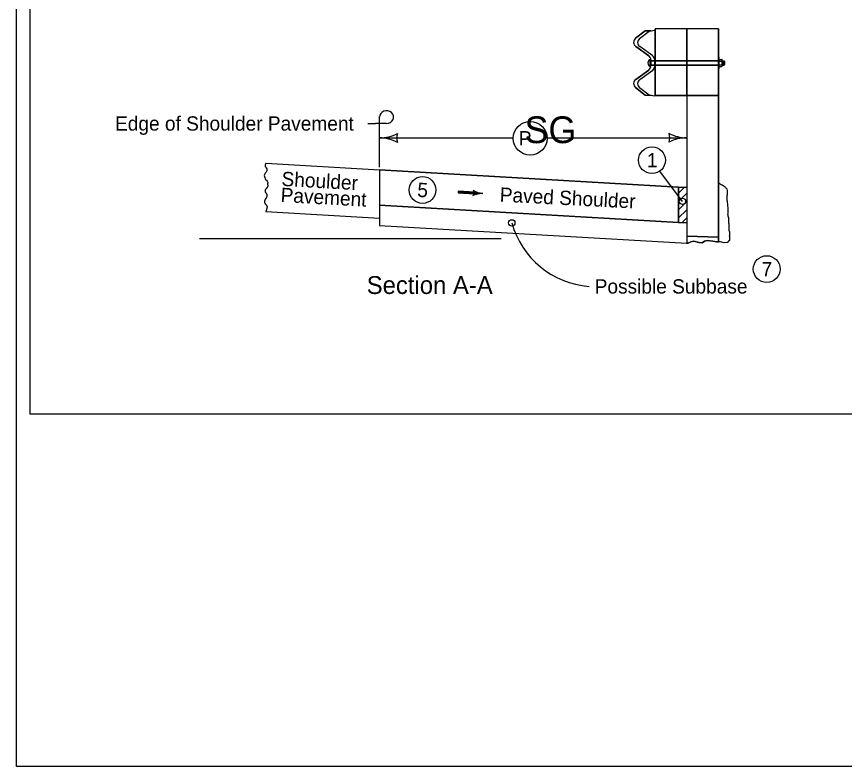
# Model space of a CAD drawing. Extents: x 9538 to 81668, y 7600 to 11751.
# Drawn here: x 24533 to 25461, y 7924 to 8764 of the extents above; entities that cross this region are included whole.
import ezdxf

# ---------------------------------------------------------------- set-up
doc = ezdxf.new("R2010")
doc.units = 0
for name, color, linetype in [('Default', 7, 'Continuous'), ('DsnShtMinorGrid13', 7, 'Continuous'), ('DsnShtMinorGrid14', 7, 'Continuous'), ('dsnStdCells', 7, 'Continuous'), ('dsnStdDimension', 7, 'Continuous'), ('dsnStdNameDate', 7, 'Continuous'), ('dsnStdNote', 7, 'Continuous'), ('dsnStdShading', 7, 'Continuous'), ('dsnStdTable', 7, 'Continuous')]:
    doc.layers.add(name, color=color, linetype=linetype)

msp = doc.modelspace()

# ---------------------------------------------------------------- linework, layer by layer
at = {"layer": 'Default'}
msp.add_lwpolyline([(24532.55, 9944.02), (27667.56, 9944.02), (27667.56, 7924.02), (24532.55, 7924.02)], close=True, dxfattribs=at)
at = {"layer": 'DsnShtMinorGrid13'}
for centre, radius in [((25244.81, 8603.28), 15), ((24987.61, 8569.91), 15), ((25278.94, 8557.17), 3.58), ((25373.4, 8481.26), 15)]:
    msp.add_circle(centre, radius, dxfattribs=at)
at = {"layer": 'DsnShtMinorGrid14'}
msp.add_circle((25087.64, 8533.07), 3.54, dxfattribs=at)
at = {"layer": 'dsnStdCells'}
for p, q in [((25226.58, 8730.73), (25241.09, 8720.31)), ((25241.09, 8704.24), (25226.58, 8693.82))]:
    msp.add_line(p, q, dxfattribs=at)
for points in [[(25230.83, 8739.63), (25230.82, 8739.62), (25241.6, 8748.02), (25243.48, 8748.36), (25237.15, 8748.24), (25226.39, 8739.85)], [(25283.87, 8714.93), (25283.87, 8750.61), (25248.33, 8750.61), (25248.33, 8714.93), (25248.33, 8714.93), (25283.87, 8714.93)], [(25319.42, 8714.93), (25319.42, 8718.93), (25319.42, 8750.61), (25283.87, 8750.61), (25283.87, 8714.93), (25319.42, 8714.93)], [(25245.54, 8720.09), (25245.57, 8720.07), (25231, 8730.53), (25231.03, 8730.51)], [(25243.49, 8715.68), (25243.49, 8714.6), (25247.93, 8714.6), (25247.93, 8715.46), (25247.93, 8715.46)], [(25248.33, 8714.6), (25248.33, 8709.93), (25248.33, 8709.93), (25283.87, 8709.93), (25283.87, 8714.6), (25248.33, 8714.6), (25248.33, 8714.6)], [(25319.42, 8709.93), (25319.42, 8714.6), (25283.87, 8714.6), (25283.87, 8709.93), (25319.42, 8709.93)], [(25247.93, 8708.65), (25247.93, 8708.65), (25247.93, 8709.93), (25243.49, 8709.93), (25243.49, 8708.87), (25243.49, 8709.93), (25243.49, 8709.93), (25243.49, 8708.87)], [(25248.33, 8709.6), (25248.33, 8675.96), (25283.87, 8675.96), (25283.87, 8709.6), (25248.33, 8709.6)], [(25319.42, 8675.96), (25319.42, 8705.6), (25319.42, 8709.6), (25283.87, 8709.6), (25283.87, 8675.96), (25319.42, 8675.96)], [(25231.03, 8693.6), (25231, 8693.58), (25245.57, 8704.04), (25245.54, 8704.02)], [(25226.39, 8684.7), (25237.15, 8676.31), (25244.26, 8675.62), (25241.6, 8676.09), (25230.82, 8684.5), (25230.83, 8684.48)], [(25319.42, 8517.01), (25319.42, 8675.96), (25283.87, 8675.96), (25283.87, 8572.99), (25283.87, 8566.3), (25283.87, 8566.3), (25283.87, 8566.3), (25283.87, 8557.07), (25283.87, 8557.07), (25283.87, 8557.07), (25283.87, 8547.93), (25283.87, 8547.93), (25283.87, 8547.93), (25283.87, 8541), (25283.87, 8518.17), (25319.42, 8517.01)], [(25319.42, 8517.01), (25283.87, 8518.17), (25283.87, 8510.15), (25285.51, 8510.38), (25288.27, 8511.97), (25291.55, 8512.5), (25297.17, 8510.91), (25300.88, 8510.69), (25303.53, 8512.5), (25306.6, 8513.13), (25312.86, 8512.39), (25317.1, 8511.97), (25319.42, 8511.97), (25319.42, 8517.01)]]:
    msp.add_lwpolyline(points, dxfattribs=at)
msp.add_lwpolyline([(25247.93, 8714.6), (25243.49, 8714.6), (25243.49, 8711.14), (25243.49, 8712.27), (25243.49, 8709.93), (25247.93, 8709.93)], close=True, dxfattribs=at)
for centre, start, end in [((25229.86, 8735.36), 127.75002, 234.69086), ((25234.31, 8735.14), 127.75002, 234.69086), ((25237.81, 8715.68), 0, 54.69099), ((25242.26, 8715.46), 0, 54.69099), ((25237.81, 8708.87), 305.30901, 0), ((25242.26, 8708.65), 305.30901, 0), ((25229.86, 8689.19), 125.30914, 232.24998), ((25234.31, 8688.97), 125.30914, 232.24998)]:
    msp.add_arc(centre, 5.68, start, end, dxfattribs=at)
at = {"layer": 'dsnStdDimension'}
for p, q in [((24939.48, 8628.24), (25089.32, 8628.24)), ((25127.17, 8628.4), (25283.87, 8628.4))]:
    msp.add_line(p, q, dxfattribs=at)
msp.add_circle((25108.24, 8627.84), 18.93, dxfattribs=at)
for centre, radius, start, end in [((24939.48, 8670.74), 42.5, 270, 298.07249), ((24975.12, 8628.24), 16.42, 162.26665, 197.73335), ((25248.24, 8628.4), 16.42, 342.26665, 17.73335), ((25283.87, 8670.9), 42.5, 241.92751, 270), ((24939.48, 8585.74), 42.5, 61.92751, 90), ((25283.87, 8585.9), 42.5, 90, 118.07249), ((25181.8, 8559.36), 97.76, 195.59781, 265.55799)]:
    msp.add_arc(centre, radius, start, end, dxfattribs=at)
at = {"layer": 'dsnStdNameDate'}
msp.add_line((25278.94, 8557.17), (25253.55, 8591.09), dxfattribs=at)
at = {"layer": 'dsnStdNote'}
for p, q in [((24939.48, 8631.56), (24939.48, 8652.42)), ((24926.11, 8644.41), (24934.8, 8644.41)), ((24947.3, 8644.41), (24934.8, 8644.41)), ((24939.48, 8595.62), (24939.48, 8631.56)), ((25045.87, 8566.52), (25027.66, 8567.57)), ((25045.77, 8565.58), (25045.77, 8565.58)), ((25045.88, 8567.53), (25045.88, 8567.53))]:
    msp.add_line(p, q, dxfattribs=at)
for points in [[(25045.9, 8567.46), (25027.73, 8568.51), (25027.6, 8566.63), (25045.77, 8565.58), (25045.82, 8567.19), (25027.95, 8568.29), (25027.89, 8566.79), (25045.38, 8565.84), (25045.51, 8566.96), (25028.18, 8568.02), (25028.16, 8567.02), (25045.17, 8566.04), (25045.26, 8566.75), (25028.37, 8567.8), (25028.36, 8567.24), (25044.96, 8566.31)], [(25045.49, 8568.72), (25046.19, 8567.55), (25046.16, 8565.9), (25045.4, 8564.51), (25048.16, 8565.37), (25051.35, 8566.02), (25052.25, 8566.16), (25050.01, 8566.7), (25046.78, 8567.93), (25045.84, 8568.47), (25045.96, 8564.95), (25050.91, 8566.17), (25046.27, 8567.75), (25046.28, 8565.33), (25049.68, 8566.26), (25046.68, 8567.12), (25046.45, 8565.74), (25048.61, 8566.24), (25047.02, 8566.75), (25046.88, 8566.09), (25047.67, 8566.25)]]:
    msp.add_lwpolyline(points, dxfattribs=at)
for centre, major_axis, start_param, end_param in [((24947.3, 8651.54), (-7.81, 0), 1.570796, 6.283185), ((25042.1, 8566.74), (3.88, 0), 5.202895, 7.237436), ((25054.37, 8545.74), (22.17, 0), 1.537172, 2.061295), ((25057.16, 8586.16), (-22.17, 0), 0.954258, 1.478381)]:
    msp.add_ellipse(centre, major_axis=major_axis, ratio=0.913811, start_param=start_param, end_param=end_param, dxfattribs=at)
at = {"layer": 'dsnStdShading'}
for p, q in [((24547.55, 9929.02), (24547.55, 8319.02)), ((24547.55, 8319.02), (27643.24, 8319.02))]:
    msp.add_line(p, q, dxfattribs=at)
at = {"layer": 'dsnStdTable'}
for p, q in [((25226.39, 8739.85), (25237.15, 8748.24)), ((25230.82, 8739.62), (25241.6, 8748.02)), ((25237.15, 8748.24), (25243.48, 8748.36)), ((25241.6, 8748.02), (25247.93, 8749.14)), ((25319.42, 8750.61), (25248.33, 8750.61)), ((25248.33, 8675.96), (25248.33, 8750.61)), ((25283.87, 8675.96), (25283.87, 8750.61)), ((25319.42, 8750.61), (25319.42, 8511.97)), ((25241.09, 8720.31), (25226.58, 8730.73)), ((25245.57, 8720.07), (25231, 8730.53)), ((25242.71, 8708.21), (25242.71, 8716.29)), ((25242.71, 8714.6), (25248.14, 8714.6)), ((25243.49, 8708.87), (25243.49, 8715.68)), ((25243.66, 8714.6), (25248.33, 8714.6)), ((25247.93, 8712.06), (25247.93, 8715.46)), ((25248.33, 8714.93), (25319.42, 8714.93)), ((25248.33, 8714.6), (25319.42, 8714.6)), ((25319.42, 8718.9), (25320.1, 8718.9)), ((25320.1, 8705.57), (25320.1, 8718.9)), ((25320.1, 8716.28), (25323.07, 8716.28)), ((25320.1, 8714.26), (25323.07, 8714.26)), ((25323.43, 8709.21), (25323.43, 8715.27)), ((25323.43, 8714.57), (25325.81, 8714.57)), ((25324.32, 8714.57), (25324.32, 8709.9)), ((25325.07, 8714.57), (25325.07, 8709.9)), ((25325.81, 8714.57), (25326.25, 8714.04)), ((25325.81, 8714.57), (25325.81, 8709.9)), ((25326.25, 8714.04), (25326.25, 8710.44)), ((25242.71, 8709.93), (25248.33, 8709.93)), ((25243.49, 8708.87), (25243.49, 8712.27)), ((25243.49, 8712.27), (25243.49, 8708.87)), ((25247.93, 8708.65), (25247.93, 8712.06)), ((25247.93, 8712.06), (25247.93, 8708.65)), ((25248.32, 8709.6), (25319.42, 8709.6)), ((25248.33, 8709.93), (25319.42, 8709.93)), ((25319.42, 8705.57), (25320.1, 8705.57)), ((25320.1, 8710.22), (25323.07, 8710.22)), ((25320.1, 8708.2), (25323.07, 8708.2)), ((25323.43, 8709.9), (25325.81, 8709.9)), ((25326.25, 8710.44), (25325.81, 8709.9)), ((25226.58, 8693.82), (25241.09, 8704.24)), ((25231, 8693.58), (25245.57, 8704.04)), ((25237.15, 8676.31), (25226.39, 8684.7)), ((25241.6, 8676.09), (25230.82, 8684.5)), ((25244.26, 8675.62), (25237.15, 8676.31)), ((25247.93, 8674.97), (25241.6, 8676.09)), ((25283.87, 8675.96), (25248.33, 8675.96)), ((25283.87, 8675.96), (25283.87, 8509.43)), ((24811.87, 8599.9), (24939.48, 8592.48)), ((24939.48, 8592.48), (24939.48, 8538.47)), ((24939.48, 8592.48), (25274.62, 8572.99)), ((25274.62, 8572.99), (24939.48, 8592.48)), ((24939.48, 8592.48), (24939.48, 8552.88)), ((25274.62, 8566.25), (25281.37, 8572.99)), ((25274.62, 8566.25), (25281.37, 8572.99)), ((25274.62, 8566.25), (25281.37, 8572.99)), ((25274.62, 8566.25), (25281.37, 8572.99)), ((25274.62, 8572.99), (25283.86, 8572.99)), ((25274.62, 8572.99), (25274.62, 8533.56)), ((25274.62, 8533.56), (25274.62, 8572.99)), ((25274.62, 8557.06), (25283.86, 8566.3)), ((25274.62, 8557.06), (25283.86, 8566.3)), ((25274.62, 8557.06), (25283.86, 8566.3)), ((25274.62, 8557.06), (25283.86, 8566.3)), ((25329.47, 8566.23), (25329.47, 8566.23)), ((25274.62, 8547.84), (25283.86, 8557.07)), ((25274.62, 8547.84), (25283.86, 8557.07)), ((25274.62, 8547.84), (25283.86, 8557.07)), ((25274.62, 8547.84), (25283.86, 8557.07)), ((25274.62, 8533.56), (24939.48, 8552.88)), ((24939.48, 8552.88), (25274.62, 8533.56)), ((25274.62, 8538.61), (25283.86, 8547.84)), ((24812.05, 8545.88), (24939.48, 8538.47)), ((24939.48, 8538.47), (24939.48, 8530.05)), ((25278.72, 8533.56), (25283.86, 8538.7)), ((24939.48, 8530.05), (25283.87, 8510.19)), ((25274.62, 8533.56), (25283.86, 8533.56)), ((24737.43, 8515.64), (25075.93, 8515.64)), ((25329.82, 8507.16), (25329.82, 8507.16))]:
    msp.add_line(p, q, dxfattribs=at)
for points in [[(25323.13, 8714.26), (25323.21, 8714.3), (25323.28, 8714.41), (25323.36, 8714.63), (25323.42, 8714.91), (25323.42, 8712.97), (25323.36, 8713.48), (25323.31, 8713.85), (25323.19, 8714.17), (25323.14, 8714.26), (25323.19, 8714.27), (25323.3, 8714.41), (25323.38, 8714.64), (25323.4, 8714.79), (25323.41, 8713.26), (25323.33, 8713.75), (25323.28, 8714.01), (25323.17, 8714.24), (25323.2, 8714.25), (25323.34, 8714.47), (25323.38, 8714.62), (25323.39, 8713.51), (25323.2, 8714.23), (25323.36, 8714.5), (25323.37, 8713.65), (25323.22, 8714.21), (25323.34, 8714.43), (25323.35, 8713.79), (25323.24, 8714.2), (25323.33, 8714.37), (25323.33, 8713.96), (25323.26, 8714.18), (25323.31, 8714.3), (25323.31, 8714.09), (25323.28, 8714.17), (25323.29, 8714.21)], [(25323.42, 8709.53), (25323.38, 8709.8), (25323.33, 8709.97), (25323.24, 8710.13), (25323.12, 8710.22), (25323.2, 8710.32), (25323.28, 8710.54), (25323.34, 8710.85), (25323.42, 8711.6), (25323.42, 8709.53), (25323.4, 8709.67), (25323.36, 8709.88), (25323.28, 8710.09), (25323.17, 8710.21), (25323.2, 8710.29), (25323.26, 8710.44), (25323.36, 8710.94), (25323.41, 8711.32), (25323.4, 8709.72), (25323.38, 8709.84), (25323.33, 8710), (25323.2, 8710.21), (25323.25, 8710.38), (25323.33, 8710.71), (25323.39, 8711.04), (25323.38, 8709.87), (25323.34, 8710), (25323.23, 8710.2), (25323.27, 8710.41), (25323.33, 8710.67), (25323.36, 8710.84), (25323.36, 8709.98), (25323.3, 8710.09), (25323.25, 8710.2), (25323.34, 8710.66), (25323.34, 8710.06), (25323.27, 8710.2), (25323.32, 8710.49), (25323.32, 8710.14), (25323.29, 8710.21), (25323.3, 8710.31), (25323.3, 8710.23)], [(25329.94, 8542.38), (25329.88, 8542.11), (25329.88, 8541.92), (25329.88, 8541.72), (25329.88, 8541.53), (25329.88, 8541.33), (25329.88, 8541.14), (25329.88, 8540.84), (25329.88, 8540.65), (25329.98, 8540.35), (25330.08, 8540.06), (25330.27, 8539.87), (25330.27, 8539.67), (25330.37, 8539.47), (25330.37, 8539.28), (25330.37, 8539.08), (25330.47, 8538.99), (25330.47, 8538.79), (25330.47, 8538.59), (25330.47, 8538.4), (25330.47, 8538.2), (25330.47, 8538.01), (25330.47, 8537.72), (25330.47, 8537.42), (25330.47, 8537.23), (25330.47, 8536.93), (25330.47, 8536.74), (25330.47, 8536.54), (25330.57, 8536.45), (25330.57, 8536.25), (25330.57, 8536.05), (25330.57, 8535.86), (25330.57, 8535.66), (25330.57, 8535.47), (25330.57, 8535.27), (25330.57, 8535.08), (25330.57, 8534.88), (25330.57, 8534.69), (25330.57, 8534.49), (25330.57, 8534.3), (25330.57, 8534.1), (25330.57, 8533.91), (25330.57, 8533.71), (25330.57, 8533.51), (25330.57, 8533.32), (25330.57, 8533.12), (25330.57, 8532.93), (25330.66, 8532.83), (25330.66, 8532.63), (25330.66, 8532.44), (25330.76, 8532.34), (25330.76, 8532.15), (25330.76, 8531.95), (25330.86, 8531.85), (25330.86, 8531.66), (25330.86, 8531.46), (25330.86, 8531.27), (25330.86, 8530.97), (25330.96, 8530.68), (25330.96, 8530.49), (25330.96, 8530.29), (25330.96, 8530.09), (25330.96, 8529.9), (25330.96, 8529.7), (25330.96, 8529.51), (25330.96, 8529.31), (25330.96, 8529.12), (25330.96, 8528.92), (25330.96, 8528.73), (25330.96, 8528.53), (25330.96, 8528.34), (25330.96, 8528.14), (25330.96, 8527.95), (25330.96, 8527.75), (25330.96, 8527.55), (25330.96, 8527.36), (25330.96, 8527.16), (25330.96, 8526.97), (25330.96, 8526.77), (25330.96, 8526.58), (25330.96, 8526.38), (25330.96, 8526.19), (25330.96, 8525.99), (25330.96, 8525.8), (25330.96, 8525.6), (25330.96, 8525.4), (25330.96, 8525.21), (25330.96, 8525.01), (25331.06, 8524.92), (25331.06, 8524.62), (25331.06, 8524.43), (25331.15, 8524.23), (25331.25, 8523.94), (25331.25, 8523.74), (25331.35, 8523.65), (25331.35, 8523.45), (25331.45, 8523.35), (25331.54, 8523.26), (25331.54, 8523.06), (25331.54, 8522.86), (25331.54, 8522.67), (25331.64, 8522.57), (25331.64, 8522.38), (25331.64, 8522.18), (25331.64, 8521.99), (25331.64, 8521.79), (25331.64, 8521.59), (25331.64, 8521.4), (25331.64, 8521.2), (25331.64, 8521.01), (25331.64, 8520.81), (25331.64, 8520.62), (25331.64, 8520.42), (25331.64, 8520.23), (25331.64, 8520.03), (25331.64, 8519.84), (25331.64, 8519.64), (25331.64, 8519.44), (25331.64, 8519.25), (25331.64, 8519.05), (25331.64, 8518.86), (25331.64, 8518.66), (25331.64, 8518.47), (25331.64, 8518.27), (25331.64, 8518.08), (25331.64, 8517.88), (25331.64, 8517.69), (25331.64, 8517.69), (25331.64, 8517.98), (25331.64, 8518.17), (25331.64, 8518.37), (25331.64, 8518.17), (25331.64, 8517.98), (25331.64, 8517.78), (25331.64, 8517.59), (25331.64, 8517.39), (25331.64, 8517.2), (25331.64, 8517), (25331.64, 8516.81), (25331.64, 8516.61), (25331.64, 8516.42), (25331.64, 8516.22), (25331.64, 8516.03), (25331.64, 8515.83), (25331.64, 8515.63), (25331.64, 8515.44), (25331.54, 8515.34), (25331.54, 8515.15), (25331.54, 8514.95), (25331.54, 8514.76), (25331.54, 8514.56), (25331.54, 8514.36), (25331.54, 8514.17), (25331.54, 8513.97), (25331.54, 8513.78), (25331.54, 8513.58), (25331.54, 8513.39), (25331.45, 8513.29), (25331.35, 8513.09), (25331.25, 8513), (25331.15, 8512.9), (25331.06, 8512.8), (25330.86, 8512.7), (25330.66, 8512.7), (25330.57, 8512.61), (25330.47, 8512.51), (25330.37, 8512.41), (25330.18, 8512.31), (25330.08, 8512.21), (25330.08, 8512.02), (25329.98, 8511.92), (25329.98, 8511.73), (25329.98, 8511.53), (25329.98, 8511.34), (25329.98, 8511.14), (25329.98, 8511.04), (25329.98, 8511.24)], [(25329.94, 8510.92), (25325.79, 8510.8), (25321.66, 8511.97), (25317.1, 8511.97), (25312.86, 8512.39), (25306.6, 8513.13), (25303.53, 8512.5), (25300.88, 8510.69), (25297.17, 8510.91), (25291.55, 8512.5), (25288.27, 8511.97), (25285.51, 8510.38), (25283.87, 8510.15)]]:
    msp.add_lwpolyline(points, dxfattribs=at)
msp.add_circle((24987.61, 8569.91), 15, dxfattribs=at)
for centre, radius, start, end in [((25229.86, 8735.36), 5.68, 127.75002, 234.69086), ((25234.31, 8735.14), 5.68, 127.75002, 234.69086), ((25244.79, 8712.26), 4.54, 117.20289, 242.8461), ((25237.81, 8715.68), 5.68, 360, 54.69099), ((25242.26, 8715.46), 5.68, 360, 54.69099), ((25237.81, 8708.87), 5.68, 305.30901, 0), ((25242.26, 8708.65), 5.68, 305.30901, 0), ((25229.86, 8689.19), 5.68, 125.30914, 232.24998), ((25234.31, 8688.97), 5.68, 125.30914, 232.24998)]:
    msp.add_arc(centre, radius, start, end, dxfattribs=at)
for centre in [(25323.07, 8715.27), (25323.07, 8709.21)]:
    msp.add_ellipse(centre, major_axis=(0, -1.01), ratio=0.362258, start_param=6.283156, end_param=9.424748, dxfattribs=at)
for points in [[(24811.87, 8599.9), (24811.37, 8596.3), (24812.41, 8594.79), (24813.27, 8592.5), (24812.67, 8590.44), (24810.76, 8588.06), (24810.24, 8586.16), (24810.76, 8583.87), (24811.63, 8581.49), (24812.67, 8580.78), (24814.05, 8578.24), (24814.04, 8577.4)], [(24812.08, 8560.29), (24812.29, 8560.54), (24812.49, 8560.8), (24812.84, 8561.36), (24813.12, 8561.95), (24813.24, 8562.26), (24813.34, 8562.57), (24813.47, 8563.19), (24813.52, 8563.81), (24813.47, 8564.4), (24813.41, 8564.68), (24813.38, 8564.81), (24813.33, 8564.94), (24813.12, 8565.32), (24812.84, 8565.68), (24812.54, 8566.05), (24812.29, 8566.45), (24812.15, 8566.73), (24812.01, 8567.01), (24811.75, 8567.59), (24811.55, 8568.15), (24811.48, 8568.45), (24811.42, 8568.74), (24811.41, 8568.87), (24811.41, 8569), (24811.56, 8569.77), (24811.77, 8570.29), (24812.03, 8570.8), (24812.47, 8571.44), (24812.99, 8571.98), (24813.51, 8572.53), (24813.74, 8572.84), (24813.94, 8573.18), (24814.14, 8573.65), (24814.3, 8574.13), (24814.4, 8574.6), (24814.44, 8574.84), (24814.45, 8574.96), (24814.46, 8575.08), (24814.41, 8575.59), (24814.26, 8576.1), (24814.21, 8576.23), (24814.15, 8576.35), (24814.1, 8576.48), (24814.08, 8576.61), (24814.04, 8577.4)], [(25329.94, 8542.38), (25330.26, 8545.29), (25330.04, 8550.15), (25329.6, 8555.9), (25328.94, 8560.33), (25329.16, 8563.64), (25329.6, 8567.84), (25328.94, 8570.94), (25326.72, 8572.93), (25324.73, 8574.7), (25322.52, 8575.81), (25320.31, 8577.13), (25319.43, 8577.8)], [(24812.08, 8560.29), (24811.86, 8560.06), (24811.62, 8559.82), (24811.38, 8559.58), (24811.2, 8559.31), (24811.06, 8559.03), (24810.92, 8558.74), (24810.66, 8558.17), (24810.55, 8557.89), (24810.45, 8557.6), (24810.38, 8557.31), (24810.35, 8557.16), (24810.33, 8557.01), (24810.34, 8556.5), (24810.47, 8555.98), (24810.68, 8555.46), (24810.94, 8554.95), (24811.38, 8554.32), (24811.9, 8553.77), (24812.42, 8553.22), (24812.65, 8552.92), (24812.85, 8552.58), (24813.25, 8551.63), (24813.36, 8551.16), (24813.37, 8550.68), (24813.33, 8550.39), (24813.28, 8550.1), (24813.23, 8549.81), (24813.16, 8549.53), (24812.85, 8548.38), (24812.67, 8547.77), (24812.47, 8547.17), (24812.25, 8546.58), (24812.12, 8546.29), (24811.98, 8546.01), (24811.9, 8545.89)]]:
    msp.add_spline(points, degree=3, dxfattribs=at)

# ---------------------------------------------------------------- texts
at = {"layer": 'DsnShtMinorGrid13'}
for s, p in [('1', (25239.19, 8595.28)), ('7', (25367.7, 8473.26))]:
    msp.add_text(s, height=16, dxfattribs=at).set_placement(p)
msp.add_text('5', height=16, rotation=356.69973, dxfattribs=at).set_placement((24981.39, 8562.26))
at = {"layer": 'dsnStdDimension'}
for s, height, p in [('SG', 30, (25101.96, 8622.4)), ('P', 16, (25095.53, 8619.84))]:
    msp.add_text(s, height=height, dxfattribs=at).set_placement(p)
at = {"layer": 'dsnStdNote'}
for s, height, p in [('Edge of Shoulder Pavement', 16, (24642.95, 8636.41)), ('Section A-A', 20, (24925.06, 8453.39)), ('Possible Subbase', 16, (25180.59, 8453.89))]:
    msp.add_text(s, height=height, dxfattribs=at).set_placement(p)
for s, rotation, p in [('Shoulder', 356.73462, (24829.24, 8574.55)), ('Pavement', 356.73462, (24828.22, 8556.58)), ('Paved Shoulder ', 357.0678, (25073.88, 8556.89))]:
    msp.add_text(s, height=16, rotation=rotation, dxfattribs=at).set_placement(p)

doc.saveas('drawing.dxf')
